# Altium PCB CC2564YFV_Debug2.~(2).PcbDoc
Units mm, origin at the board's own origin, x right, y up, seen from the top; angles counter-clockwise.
Board outline 229.87 x 45.72 mm, 2 copper layers (Top Layer, Bottom Layer); 42 components, 48 nets, 258 pads, 54 vias.
Unrouted connection lines stored in the file: 3.
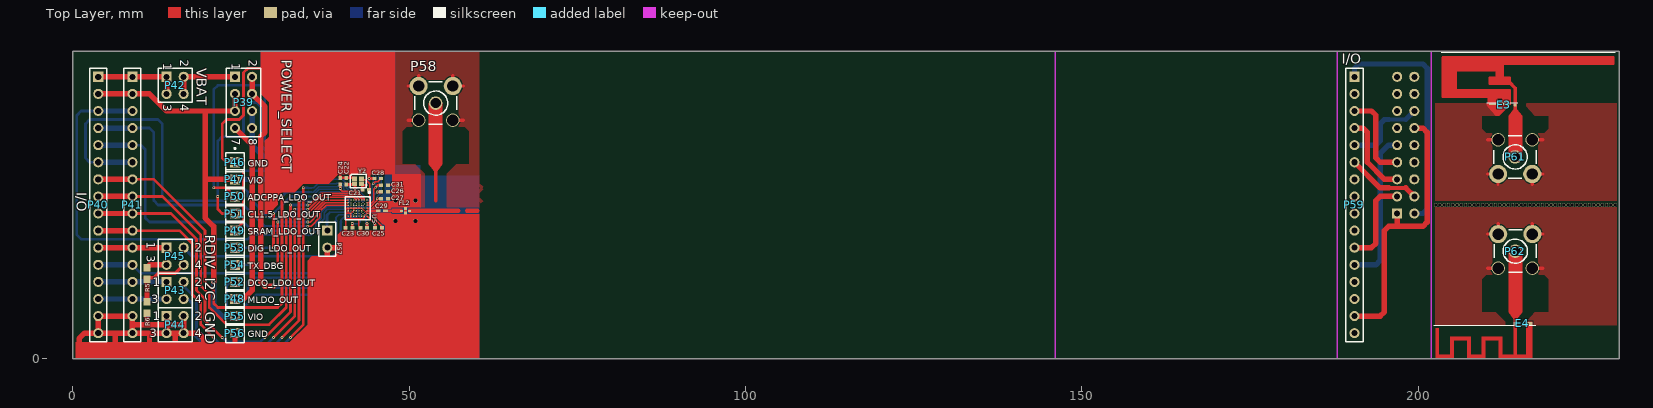
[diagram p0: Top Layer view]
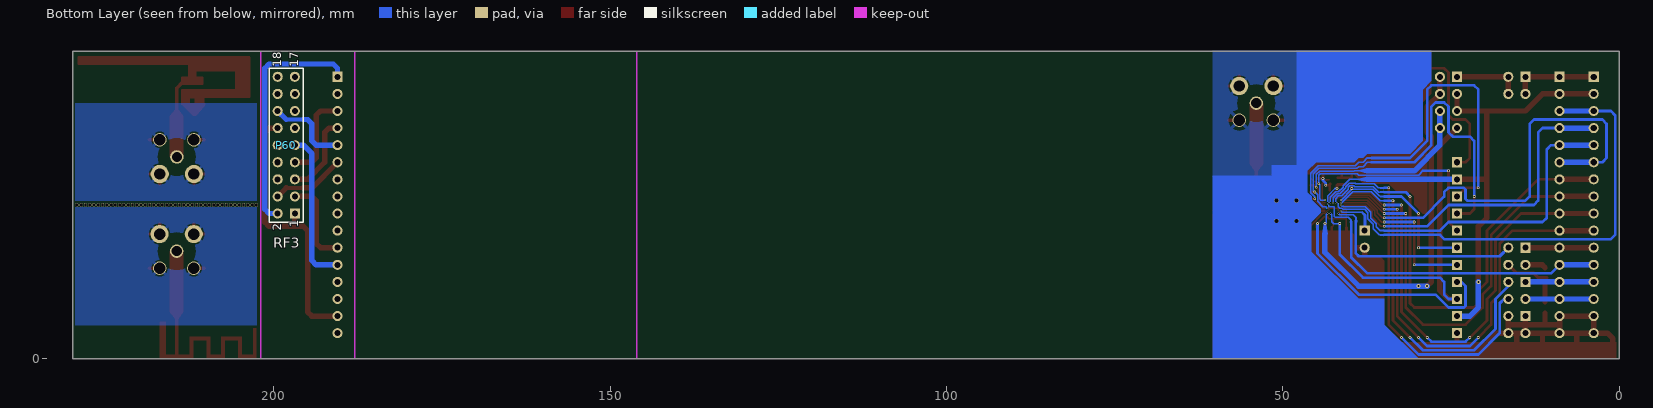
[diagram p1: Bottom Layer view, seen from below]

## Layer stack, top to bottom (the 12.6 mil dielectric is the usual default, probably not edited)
Top Solder: solder mask 0.0102, Solder Resist, Dk 3.5
Top Layer: signal copper 0.0356
Dielectric 1: dielectric 0.32, FR-4, Dk 4.8
Bottom Layer: signal copper 0.0356
Bottom Solder: solder mask 0.0102, Solder Resist, Dk 3.5

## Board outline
0,0 229.87,0 229.87,45.72 0,45.72

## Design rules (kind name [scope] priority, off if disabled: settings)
Clearance [All] p1: gap=0.1
ComponentClearance [All] p1 off: gap=0.1 collisioncheckmode=3 verticalgap=0.1 showdistances=FALSE
HoleSize [All] p1: absolutevalues=TRUE maxlimit=2.54 minlimit=0.1 maxpercent=80.000 minpercent=20.000
HoleToHoleClearance [All] p1: gap=0.1 allowstackedmicrovias=TRUE
MinimumSolderMaskSliver [All] p1: minsoldermaskwidth=0.1
PolygonConnect [All] p1: connectstyle=Relief reliefconductorwidth=0.5 reliefentries=4 polygonreliefangle="45 Angle" airgapwidth=0.2
RoutingVias [All] p1: holewidth=0.2 width=0.25 viastyle="Through Hole" minholewidth=0.1 minwidth=0.25 maxholewidth=0.2 maxwidth=0.45
SilkToSilkClearance [All] p1: silktosilkclearance=0.1
SilkToSolderMaskClearance [IsPad] p1 off: minsilkscreentomaskgap=0.1 clearancetoexposedcopper=TRUE
SolderMaskExpansion [All] p1: expansion=0.102
Width [All] p1: maxlimit=6 minlimit=0.1 preferedwidth=0.2
23 further rules are at their usual default settings.

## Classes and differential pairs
component class CC2564YFV_Debug2_RF: C21 C22 C23 C24 C25 C26 C27 C28 C29 C30 C31 FL2 P39 P40 P41 P42 P43 P44 P45 P46 P47 P48 P49 P50 P51 P52 P53 P54 P55 P56 P57 P58 R5 R6 U5 Y2
component class CC2564YFV_Debug2_Add: E3 E4 P59 P60 P61 P62

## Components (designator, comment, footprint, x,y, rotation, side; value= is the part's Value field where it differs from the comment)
C21 "Cap Semi 8 pF" 0402 43.56,25.1 r0 top
C22 "Cap Semi 8 pF" 0402 40.66,26.4 r270 top
C23 "C1005X5R1A105K050BB" 0402 41.06,19.5 r0 top
C24 "C1005X7R1H104M050BB" 0402 39.76,26.4 r270 top
C25 "C1005X7R1H104M050BB" 0402 45.46,19.5 r180 top
C26 "C1005X7R1H104M050BB" 0402 46.36,24.8 r180 top
C27 "C1005X7R1H104M050BB" 0402 46.36,23.8 r180 top
C28 "C1005X7R1H104M050BB" 0402 45.36,26.8 r0 top
C29 "GRM0335C1E220JA01D" 1-0201 45.96,22 r0 top
C30 "C1005X7R1H104M050BB" 0402 43.26,19.5 r0 top
C31 "C1005X5R1A105K050BB" 0402 46.36,25.8 r180 top
E3 "Inverted F Antenna" Inverted_F_Antenna 214.38,37.7 r0 top
E4 "Meandered IFA" Meandered_IFA 216.95,5 r180 top
FL2 "FI105L250014" FL105_Electrodes 49.46,22 r0 top
P39 "POWER_SELECT" HDR2X4 24.13,41.91 r270 top
P40 "I/O" HDR1X16 3.81,41.91 r270 top
P41 "I/O" HDR1X16 8.89,41.91 r270 top
P42 "VBAT" HDR2X2 13.97,41.91 r270 top
P43 "I2C" HDR2X2 13.97,11.43 r270 top
P44 "GND" HDR2X2 13.97,6.35 r270 top
P45 "RDIV" HDR2X2 13.97,16.51 r270 top
P46 "GND" PIN1 24.13,29.21 r0 top
P47 "VIO" PIN1 24.13,26.67 r0 top
P48 "MLDO_OUT" PIN1 24.13,8.89 r0 top
P49 "SRAM_LDO_OUT" PIN1 24.13,19.05 r0 top
P50 "ADCPPA_LDO_OUT" PIN1 24.13,24.13 r0 top
P51 "CL1.5_LDO_OUT" PIN1 24.13,21.59 r0 top
P52 "DCO_LDO_OUT" PIN1 24.13,11.43 r0 top
P53 "DIG_LDO_OUT" PIN1 24.13,16.51 r0 top
P54 "TX_DBG" PIN1 24.13,13.97 r0 top
P55 "VIO" PIN1 24.13,6.35 r0 top
P56 "GND" PIN1 24.13,3.81 r0 top
P57 "G5" HDR1X2 37.846,19.05 r270 top
P58 "SMA" SMA#1 53.96,38 r0 top
P59 "I/O" HDR1X16 190.5,41.91 r270 top
P60 "RF3" HDR2X9 196.85,21.59 r90 bottom
P61 "SMA" SMA#2 214.38,30 r0 top
P62 "SMA" SMA#1 214.4,16 r0 top
R5 "Res Chip 10 K" 3-0603 11.049,12.7 r90 top
R6 "Res Chip 12 K" 3-0603 11.049,7.62 r90 top
U5 "CC2564YFV" "YFV (R-XBGA-N54)" 42.36,22.2 r270 top
Y2 "NX1612AA-26MHZ-TI2" XTAL_QUAD_1.6x1.2mm 42.435,26.375 r180 top

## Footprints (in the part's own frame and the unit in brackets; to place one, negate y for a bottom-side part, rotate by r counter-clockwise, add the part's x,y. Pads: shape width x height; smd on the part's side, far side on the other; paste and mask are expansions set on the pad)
1-0201 [mm] "Chip Resistor; Body 0.6 x 0.3 mm (LxW typ)"
  rect 0.7x0.4 smd: 1(-0.525,0) 2(0.525,0)
3-0603 [mm] "Chip Resistor; Body 1.6 x 0.9 mm (LxW typ)"
  rect 1.1x1 smd: 1(-0.85,0) 2(0.85,0)
0402 [mm] "Chip Capacitor, Body 1.0x0.5mm, IPC High Density"
  rect 0.6x0.5 smd: 1(-0.5,0) 2(0.5,0)
  body extent -0.55,-0.3 0.55,0.3, height 1.3
FL105_Electrodes [mm]
  round 0.6 hole 0.6: 1(-1.5,1.5) 1(1.5,1.5) 3(-1.5,-1.5) 3(1.5,-1.5)
  rect 0.4x0.45 smd: 1(0,0.35) 3(0,-0.35)
  rect 0.45x0.3 smd: 2(0.575,0) 4(-0.575,0)
  Top Layer region: -0.2,-0.5 0.2,-0.5 0.2,0.5 -0.2,0.5
  Top Layer region: 0.5,-0.3 2,-0.3 2,0.3 0.5,0.3
  Top Layer region: -2,-0.3 -0.5,-0.3 -0.5,0.3 -2,0.3
  Top Layer region: -2,-2 2,-2 2,-0.5 -2,-0.5
  Top Layer region: -2,0.5 2,0.5 2,2 -2,2
  Top Layer region: -0.5,0.3 -0.425,0.15 -0.5,0.15
  Top Layer region: 0.425,0.15 0.5,0.3 0.5,0.15
  Top Layer region: -0.425,-0.15 -0.5,-0.3 -0.5,-0.15
  Top Layer region: 0.425,-0.15 0.5,-0.3 0.5,-0.15
HDR1X2 [mm] "Connector; Header; 2 Position"
  rect 1.5x1.5 hole 0.9: 1(0,0)
  round 1.5 hole 0.9: 2(2.54,0)
  silkscreen extent -1.27,-1.27 3.81,1.27
HDR1X16 [mm] "Connector; Header; 16 Position"
  rect 1.5x1.5 hole 0.9: 1(0,0)
  round 1.5 hole 0.9: 2(2.54,0) 3(5.08,0) 4(7.62,0) 5(10.16,0) 6(12.7,0) 7(15.24,0) 8(17.78,0) 9(20.32,0) 10(22.86,0) 11(25.4,0) 12(27.94,0) 13(30.48,0) 14(33.02,0) 15(35.56,0) 16(38.1,0)
  silkscreen extent -1.27,-1.27 39.37,1.27
HDR2X2 [mm] "Connector; Header; 2x2 Position"
  rect 1.5x1.5 hole 0.9: 1(0,0)
  round 1.5 hole 0.9: 2(0,2.54) 3(2.54,0) 4(2.54,2.54)
  silkscreen extent -1.27,-1.27 3.81,3.81
HDR2X4 [mm] "Connector; Header; 4x2 Position"
  rect 1.5x1.5 hole 0.9: 1(0,0)
  round 1.5 hole 0.9: 2(0,2.54) 3(2.54,0) 4(2.54,2.54) 5(5.08,0) 6(5.08,2.54) 7(7.62,0) 8(7.62,2.54)
  silkscreen extent -1.27,-1.27 8.89,3.81
HDR2X9 [mm] "Connector; Header; 9x2 Position"
  rect 1.5x1.5 hole 0.9: 1(0,0)
  round 1.5 hole 0.9: 2(0,2.54) 3(2.54,0) 4(2.54,2.54) 5(5.08,0) 6(5.08,2.54) 7(7.62,0) 8(7.62,2.54) 9(10.16,0) 10(10.16,2.54) 11(12.7,0) 12(12.7,2.54) 13(15.24,0) 14(15.24,2.54) 15(17.78,0) 16(17.78,2.54) 17(20.32,0) 18(20.32,2.54)
  silkscreen extent -1.27,-1.27 21.59,3.81
Inverted_F_Antenna [mm]
  round 0.46 smd mask+0: 1(0,0)
  rect 1x0.3 smd paste+0 mask+0: 2(-1.272,0.165) 3(-3.367,0.183)
  Top Layer region: -10.77,1.092 -10.237,1.092 -4.039,1.067 -4.039,0.127 -4.032,0.088 -4.009,0.055 -3.976,0.033 -3.937,0.025 -3.937,0.025 -2.788,0.025 -2.749,0.033 -2.716,0.055 -2.694,0.088 -2.686,0.127 -2.686,0.127 -2.686,1.025 -1.89,1.025 -1.89,0.127 -1.882,0.088 -1.86,0.055 -1.827,0.033 -1.788,0.025 -1.788,0.025 -0.788,0.025 -0.767,0.027 -0.747,0.033 -0.747,0.033 -0.702,0.051 -0.669,0.087 -0.658,0.135 -0.658,0.135 -0.658,0.135 -0.658,0.135 -0.658,0.135 -0.66,2.23 -0.67,2.274 -0.698,2.309 -0.698,2.309 -0.698,2.309 -0.721,2.338 -0.752,2.356 -0.788,2.363 -0.788,2.363 -8.686,2.363 -8.686,5.025 -2.89,5.025 -2.89,4.229 -3.788,4.229 -3.827,4.221 -3.86,4.199 -3.882,4.166 -3.89,4.127 -3.89,4.127 -3.89,3.127 -3.882,3.088 -3.86,3.055 -3.827,3.033 -3.788,3.025 -3.788,3.025 -0.83,3.025 -0.231,2.426 -0.231,0 -0.208,-0.1 -0.144,-0.18 -0.052,-0.225 0.051,-0.225 0.143,-0.18 0.207,-0.1 0.23,0 0.23,0 0.23,2.521 0.212,2.61 0.162,2.685 0.162,2.685 -0.686,3.533 -0.686,4.127 -0.694,4.166 -0.716,4.199 -0.749,4.221 -0.788,4.229 -0.788,4.229 -1.686,4.229 -1.686,6.025 14.63,6.025 14.669,6.033 14.702,6.055 14.724,6.088 14.732,6.127 14.732,6.127 14.732,7.137 14.724,7.176 14.702,7.21 14.669,7.232 14.63,7.239 14.63,7.239 -10.77,7.239 -10.809,7.232 -10.842,7.21 -10.864,7.176 -10.872,7.137 -10.872,7.137 -10.872,1.194 -10.864,1.155 -10.842,1.122 -10.809,1.1 -10.77,1.092
  silkscreen extent -11,0.34 14.9,7.86
Meandered_IFA [mm] "Meandered Inverted F Antenna"
  rect 0.5x0.5 smd mask+0: 1(2.55,-0.25)
  rect 0.9x0.5 smd mask+0: 2(0.45,-0.25)
  Top Layer region: 0,-0.5 0,4.89 5,4.89 5,2.25 7,2.25 7,4.89 9.7,4.89 9.7,2.25 11.7,2.25 11.7,4.89 14.4,4.89 14.4,0.45 13.9,0.45 13.9,4.39 12.2,4.39 12.2,1.75 9.2,1.75 9.2,4.39 7.5,4.39 7.5,1.75 4.5,1.75 4.5,4.39 2.8,4.39 2.8,-0.5 2.3,-0.5 2.3,4.39 0.9,4.39 0.9,-0.5
  silkscreen extent -0.5,0 14.7,0
PIN1 [mm] "Connector; Plug"
  rect 1.5x1.5 hole 0.9: 1(0,0)
  silkscreen extent -1.4,-1.4 1.4,2.17
SMA#1 [mm] "Connector; SMA Generic"
  round 2 hole 1.5: 1(0,0)
  round 2 hole 1.7: 2(-2.54,-2.54) 2(2.54,-2.54)
  round 2.7 hole 1.7: 2(-2.54,2.54) 2(2.54,2.54)
  silkscreen extent -3.15,-3.15 3.15,3.15
SMA#2 [mm] "Connector; SMA Generic"
  round 2 hole 1.5: 1(0,0)
  round 2.7 hole 1.7: 2(-2.54,-2.54) 2(2.54,-2.54)
  round 2 hole 1.7: 2(-2.54,2.54) 2(2.54,2.54)
  silkscreen extent -3.15,-3.15 3.15,3.15
XTAL_QUAD_1.6x1.2mm [mm]
  rect 0.75x0.65 smd: 1(-0.525,-0.375) 2(0.525,-0.375) 3(0.525,0.375) 4(-0.525,0.375)
  silkscreen extent -1.2,-1.02 1.2,0.98
"YFV (R-XBGA-N54)" [mm] "BGA, 54-Balls, Pitch 0.4mm"
  round 0.2 smd: A1(-1.4,1.4) A2(-1,1.4) A3(-0.6,1.4) A4(-0.2,1.4) A5(0.2,1.4) A6(0.6,1.4) A7(1,1.4) B1(-1.4,1) B2(-1,1) B3(-0.6,1) B4(-0.2,1) B6(0.6,1) B7(1,1) C1(-1.4,0.6) C2(-1,0.6) C3(-0.6,0.6) C4(-0.2,0.6) C5(0.2,0.6) C6(0.6,0.6) C7(1,0.6) D1(-1.4,0.2) D2(-1,0.2) D3(-0.6,0.2) D4(-0.2,0.2) D5(0.2,0.2) D6(0.6,0.2) D7(1,0.2) E1(-1.4,-0.2) E2(-1,-0.2) E3(-0.6,-0.2) E4(-0.2,-0.2) E5(0.2,-0.2) E6(0.6,-0.2) E7(1,-0.2) F1(-1.4,-0.6) F2(-1,-0.6) F3(-0.6,-0.6) F4(-0.2,-0.6) F5(0.2,-0.6) F6(0.6,-0.6) F7(1,-0.6) G1(-1.4,-1) G2(-1,-1) G3(-0.6,-1) G4(-0.2,-1) G5(0.2,-1) G6(0.6,-1) G7(1,-1) H1(-1.4,-1.4) H2(-1,-1.4) H3(-0.6,-1.4) H4(-0.2,-1.4) H5(0.2,-1.4) H7(1,-1.4)
  silkscreen extent -2.65,-1.88 1.52,1.88, body extent -1.91,-1.91 1.52,1.91, height 0.5

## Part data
C21 C22: "Chip Capacitor, 8 pF"
C23 C31: "1.0 uF/10 V 0402"
C24 C25 C26 C27 C28 C30: "0.1 uF/50 V 0402"
C29: "22 pF/25 V 0201"
E3: "Inverted F Antenna (Design Note DN0007; SWRU120B)"
E4: "Meandered Inverted F Antenna (Application Note AN043; SWRA117D)"
FL2: "2.4 GHz Low Pass Filter"
P39: library part "Header 4X2", "Header, 4-Pin, Dual row"
P40 P41 P59: library part "Header 16", "Header, 16-Pin"
P42 P43 P44 P45: library part "Header 2X2", "Header, 2-Pin, Dual row"
P46 P47 P48 P49 P50 P51 P52 P53 P54 P55 P56: library part Plug, "Plug"
P57: library part "Header 2", "Header, 2-Pin"
P58 P61 P62: "SMA Generic Connector"
P60: library part "Header 9X2", "Header, 9-Pin, Dual row"
R5: "Chip Resistor, 10 K"
R6: "Chip Resistor, 12 K"
U5: "CC2564, 54-balls DSBGA"
Y2: "Crystal Oscillator 26 MHz"

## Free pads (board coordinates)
  round 0.5 hole 0.5 paste+0 mask+0: 0(202.565,22.86) 0(203.2,22.86) 0(203.835,22.86) 0(204.47,22.86) 0(205.105,22.86) 0(205.74,22.86) 0(206.375,22.86) 0(207.01,22.86) 0(207.645,22.86) 0(208.28,22.86) 0(208.915,22.86) 0(209.55,22.86) 0(210.185,22.86) 0(210.82,22.86) 0(211.455,22.86) 0(212.09,22.86) 0(212.725,22.86) 0(213.36,22.86) 0(213.995,22.86) 0(214.63,22.86) 0(215.265,22.86) 0(215.9,22.86) 0(216.535,22.86) 0(217.17,22.86) 0(217.805,22.86) 0(218.44,22.86) 0(219.075,22.86) 0(219.71,22.86) 0(220.345,22.86) 0(220.98,22.86) 0(221.615,22.86) 0(222.25,22.86) 0(222.885,22.86) 0(223.52,22.86) 0(224.155,22.86) 0(224.79,22.86) 0(225.425,22.86) 0(226.06,22.86) 0(226.695,22.86) 0(227.33,22.86) 0(227.965,22.86) 0(228.6,22.86) 0(229.235,22.86)

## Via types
v1: diameter 0.4, hole 0.2, Top Layer to Bottom Layer, 36 vias
v2: diameter 0.25, hole 0.1, Top Layer to Bottom Layer, 15 vias
v3: diameter 0.6, hole 0.3, Top Layer to Bottom Layer, 3 vias

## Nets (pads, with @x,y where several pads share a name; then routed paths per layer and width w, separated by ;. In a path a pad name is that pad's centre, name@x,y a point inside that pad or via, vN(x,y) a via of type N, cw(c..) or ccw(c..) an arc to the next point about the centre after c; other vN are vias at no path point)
ADCPPA_LDO_OUT_2: C27.2 P50.1 U5.A4 | length 60
  Top Layer w0.2: U5.A4 44.06,22.4 v1@45.26,23.6
  Top Layer w0.4: v1(20.955,25.4) 22.86,25.4 P50.1 ; v1(45.26,23.8) C27.2
  Bottom Layer w0.2: 36.83,29.845 37.465,29.845 38.1,29.21 38.735,29.21 39.245,28.7 44.76,28.7 45.86,27.6 45.86,24.7 45.26,24.1 v1(45.26,23.8)
  Bottom Layer w0.4: v1(20.955,25.4) 20.955,40.005 21.59,40.64 27.94,40.64 28.575,40.005 28.575,32.385 31.115,29.845 36.83,29.845
ANTENNA: FL2.2 P58.1 | length 12.9
  Top Layer w0.5: 53.96,23.45 53.96,29.5
  Top Layer w0.6: 50.46,22 57.31,22
AUD_CLK_2: P40.8 P41.8 U5.E1 | length 68
  Top Layer w0.2: v1(34.925,21.59) 34.95,21.59 37.36,24 41.784,24 42.16,23.624 U5.E1
  Top Layer w0.4: P41.8 13.335,24.13 19.05,18.415 19.05,10.795 20.32,9.525 20.32,7.62 22.86,5.08 29.21,5.08 31.75,7.62 v1(31.75,21.59)
  Top Layer w0.8: P40.8 P41.8
  Bottom Layer w0.4: v1(31.75,21.59) v1(34.925,21.59)
AUD_FSYNC_2: P40.7 P41.7 U5.E2 | length 70.2
  Top Layer w0.4: P41.7 12.065,26.67 19.685,19.05 19.685,11.43 20.955,10.16 20.955,8.255 21.59,7.62 30.48,7.62 31.115,8.255 v1(31.115,24.13)
  Top Layer w0.8: P40.7 P41.7
  Bottom Layer w0.2: 34.925,24.765 35.725,24.765 36.56,25.6 39.36,25.6 39.46,25.7 40.06,25.7 40.26,25.5 40.26,25.2 41.26,24.2 41.76,24.2 42.16,23.8 v2(42.16,23.2)
  Bottom Layer w0.4: v1(31.115,24.13) 31.75,24.765 34.925,24.765
AUD_IN_2: P40.9 P41.9 U5.C1 | length 72.3
  Top Layer w0.2: v1(34.925,22.86) 35.22,22.86 36.96,24.6 42.136,24.6 42.96,23.776 U5.C1
  Top Layer w0.4: P41.9 14.605,21.59 18.415,17.78 18.415,10.16 19.685,8.89 19.685,5.715 v1(22.225,3.175) ; v1(28.575,3.175) 32.385,6.985 v1(32.385,22.86)
  Top Layer w0.8: P40.9 P41.9
  Bottom Layer w0.4: v1(22.225,3.175) 22.86,2.54 27.94,2.54 v1(28.575,3.175) ; v1(32.385,22.86) v1(34.925,22.86)
AUD_OUT_2: P40.10 P41.10 U5.D1 | length 71.1
  Top Layer w0.2: v1(34.925,22.225) 35.085,22.225 37.16,24.3 41.96,24.3 42.56,23.7 U5.D1
  Top Layer w0.4: P41.10 15.875,19.05 17.78,17.145 17.78,9.525 19.05,8.255 19.05,5.08 v1(20.955,3.175) ; v1(29.845,3.175) 33.02,6.35 v1(33.02,22.225)
  Top Layer w0.8: P40.10 P41.10
  Bottom Layer w0.4: v1(20.955,3.175) 22.225,1.905 28.575,1.905 v1(29.845,3.175) ; v1(33.02,22.225) v1(34.925,22.225)
BT_CTS_2: P40.6 P41.6 U5.H1 | length 68.1
  Top Layer w0.2: v1(34.925,20.955) 35.215,20.955 35.96,21.7 35.96,22.1 37.46,23.6 U5.H1
  Bottom Layer w0.4: P40.6 2.54,29.21 1.905,29.845 1.905,34.925 2.54,35.56 12.7,35.56 13.335,34.925 13.335,24.13 13.97,23.495 22.606,23.495 22.86,23.749 22.86,25.146 23.114,25.4 25.4,25.4 26.035,24.765 26.035,24.13 29.21,20.955 v1(34.925,20.955)
  Bottom Layer w0.8: P40.6 P41.6
BT_CTS_3: P59.6 P60.4 | length 11
  Top Layer w0.6: 195.58,25.4 198.12,25.4
  Top Layer w0.8: P59.6 194.31,25.4 195.58,25.4 ; 198.12,25.4 P60.4
BT_RTS_2: P40.5 P41.5 U5.G3 | length 51.1
  Bottom Layer w0.2: 34.925,19.05 35.56,19.05 36.16,19.65 36.16,20.1 36.96,20.9 36.96,21.8 37.76,22.6 40.96,22.6 41.06,22.7 41.26,22.7 v2(41.36,22.8)
  Bottom Layer w0.4: P41.5 10.16,31.75 10.795,31.115 10.795,20.955 11.43,20.32 25.4,20.32 26.67,19.05 34.925,19.05
  Bottom Layer w0.8: P40.5 P41.5
BT_RTS_3: P59.5 P60.14 | length 12.5
  Bottom Layer w0.6: 195.58,35.56 198.12,35.56
  Bottom Layer w0.8: P59.5 193.675,31.75 194.31,32.385 194.31,34.925 194.945,35.56 195.58,35.56 ; 198.12,35.56 P60.14
BT_RX_2: P40.4 P41.4 U5.H3 | length 50.8
  Top Layer w0.2: v1@35.06,19.7 35.46,19.7 36.76,21 36.76,21.9 37.66,22.8 U5.H3
  Bottom Layer w0.4: P41.4 11.43,34.29 12.065,33.655 12.065,23.495 12.7,22.86 25.4,22.86 28.575,19.685 v1(34.925,19.685)
  Bottom Layer w0.8: P40.4 P41.4
BT_RX_3: P59.4 P60.5 | length 12.1
  Top Layer w0.8: P59.4 191.77,34.29 192.405,33.655 192.405,29.21 194.945,26.67 P60.5
BT_SHUTD_2: P40.12 P41.12 U5.B3 | length 48.3
  Bottom Layer w0.2: 39.86,20.3 39.86,20.6 40.26,21 42.26,21 42.36,21.1 42.36,22.5 42.46,22.6 43.1,22.6 43.3,22.8 v2(43.36,22.8)
  Bottom Layer w0.4: P41.12 10.16,12.7 37.465,12.7 39.86,15.095 39.86,20.3
  Bottom Layer w0.8: P40.12 P41.12
BT_SHUTD_3: P59.12 P60.9 | length 23
  Bottom Layer w0.8: P59.12 193.675,13.97 194.31,14.605 194.31,30.48 195.58,31.75 P60.9
BT_TX_2: P40.3 P41.3 U5.F2 | length 70.6
  Bottom Layer w0.2: 34.925,18.415 35.675,18.415 36.56,19.3 36.56,20 37.36,20.8 37.36,21.7 37.86,22.2 41.06,22.2 41.26,22.4 41.56,22.4 41.76,22.6 v2(41.76,23.2)
  Bottom Layer w0.4: P40.3@3.175,36.83 1.27,36.83 0.635,36.195 0.635,18.415 1.27,17.78 26.035,17.78 26.67,18.415 34.925,18.415
  Bottom Layer w0.8: P40.3 P41.3
BT_TX_3: P59.3 P60.7 | length 13.2
  Top Layer w0.8: P59.3 193.04,36.83 193.675,36.195 193.675,29.845 194.31,29.21 P60.7
CL1.5_LDO_IN_2: C30.2 P39.2 P39.4 U5.B6 | length 57.5
  Top Layer w0.4: C30.2 v1(43.76,20.1)
  Top Layer w0.8: P39.2 P39.4 28.575,37.465 28.575,33.655 27.94,33.02 27.94,11.43 v3(28.575,10.795) v3(29.845,10.795)
  Bottom Layer w0.2: v2(43.36,21.6) 43.56,21.4 43.56,20.3 v1(43.76,20.1)
  Bottom Layer w0.4: 43.76,18.5 v1(43.76,20.1)
  Bottom Layer w0.8: v3(28.575,10.795) 38.735,10.795 43.76,15.82 43.76,18.5
CL1.5_LDO_OUT_2: C26.2 P51.1 U5.B4 | length 56
  Top Layer w0.4: v1(21.59,24.13) 21.59,22.225 22.225,21.59 P51.1 ; v1(45.26,24.8) C26.2
  Bottom Layer w0.2: 36.83,29.21 37.465,29.21 38.1,28.575 38.735,28.575 39.01,28.3 44.66,28.3 45.46,27.5 45.46,25 v1(45.26,24.8) 44.86,24.4 44.86,23.4 44.06,22.6 43.66,22.6 43.46,22.4 v2(43.36,22.4)
  Bottom Layer w0.4: v1(21.59,24.13) 21.59,32.385 22.225,33.02 24.765,33.02 25.4,33.655 25.4,37.465 26.035,38.1 27.305,38.1 27.94,37.465 27.94,31.75 30.48,29.21 36.83,29.21
DCO_LDO_OUT_2: C25.2 P52.1 U5.A7 | length 36.4
  Top Layer w0.2: U5.A7 v1@44.96,20
  Top Layer w0.4: C25.2@44.96,19.6 v1@44.96,20
  Bottom Layer w0.4: P52.1 23.495,11.43 22.86,10.795 22.86,7.874 23.114,7.62 25.4,7.62 27.305,9.525 38.735,9.525 44.86,15.65 v1(44.86,20.1)
DIG_LDO_OUT_2: C24.2 P53.1 U5.B1 U5.G1 | length 29.6
  Top Layer w0.2: v1@39.76,25.2 40.06,24.9 42.26,24.9 43.36,23.8 U5.B1
  Top Layer w0.4: v1(29.845,16.51) v1(29.845,21.59) ; v1(39.76,25.3) C24.2 C24.2@39.76,26
  Bottom Layer w0.2: 34.925,24.13 35.56,24.13 ; 35.59,24.13 36.66,25.2 v1@39.76,25.2 ; v1(39.76,25.3) v1@39.76,25.2 ; v2(41.36,23.6) v1@39.76,25.2
  Bottom Layer w0.4: P53.1 v1(29.845,16.51) ; v1(29.845,21.59) 32.385,24.13 34.925,24.13
GND_2: C21.1 C22.1 C23.1 C24.1 C25.1 C26.1 C27.1 C28.1 C30.1 C31.1 FL2.1 FL2.3 P40.15 P40.16 P41.15 P41.16 P44.1 P44.2 P44.3 P44.4 P46.1 P56.1 P57.2 P58.2 R6.1 U5.A6 U5.B7 U5.C4 U5.D4 U5.E4 U5.F4 U5.F5 U5.G4 U5.G6 U5.G7 U5.H4 U5.H5 Y2.2 Y2.4 | length 115.3
  Top Layer w0.1: U5.C4 U5.A6
  Top Layer w0.11: 41.46,21.7 41.66,21.9 ; 43.46,21.3 43.66,21.5
  Top Layer w0.15: U5.G6 41.46,21.7 ; 41.66,21.9 U5.F5
  Top Layer w0.18: U5.B7 43.46,21.3 ; 43.66,21.5 U5.A6
  Top Layer w0.2: C23.1 40.56,20.8 ; 40.96,21.6 U5.H5 U5.H4 ; U5.F5 U5.F4 ; C30.1@42.56,19.7 42.56,20.8 ; U5.C4 U5.D4 U5.E4 U5.F4 ; U5.B7 43.36,21 43.16,20.8 42.56,20.8 ; U5.A6 44.06,21.6 45.96,19.7 C25.1 ; 40.56,20.8 41.36,20.8 ; 40.56,20.8 40.56,21.6 ; 40.56,21.6 U5.G6 U5.G7 41.36,20.8 ; 40.56,21.6 40.56,22.2 40.76,22.4 U5.H4 ; U5.H4 U5.G4 U5.F4 ; 41.36,20.8 42.56,20.8
  Top Layer w0.3: C27.1 47.76,23.8 ; C26.1 47.66,24.8 ; C31.1 47.76,25.8
  Top Layer w0.4: P46.1 22.86,29.21 22.225,29.845 22.225,34.925 22.86,35.56 24.765,35.56 25.4,36.195 25.4,42.545 26.035,43.18 29.845,43.18 ; 39.76,27.5 C24.1 Y2.2@41.81,26.9 ; 40.56,18.495 C23.1 ; 41.26,26.9 41.26,27.5 ; 42.76,18.495 C30.1 ; Y2.4 Y2.4@43.06,25.9 ; C21.1 Y2.4@43.06,25.9 ; v1(43.66,25.8) 43.16,25.8 Y2.4@43.06,25.9 ; 44.06,27.5 v1(44.06,26.8) C28.1 ; 45.96,18.495 C25.1
  Top Layer w0.5: 49.862,35.46 P58.2@51.42,35.46 ; 49.862,40.54 51.42,40.54 51.42,42.098 ; P58.2@56.5,35.46 58.057,35.46 ; 56.5,42.098 56.5,40.54 58.057,40.54
  Top Layer w0.8: 0.96,2.5 0.96,3 1.77,3.81 P40.16 ; 6.35,2.54 6.35,3.81 ; 11.049,5.461 R6.1 ; 11.43,2.54 11.43,3.81 ; P44.1 13.97,5.08 ; 15.24,2.54 15.24,3.81 ; P44.2 16.51,5.08 ; 19.46,2.5 19.46,3 18.65,3.81 P44.4 ; 24.13,2.54 P56.1 ; 37.846,14.224 P57.2 39.37,16.51 ; P40.16 6.35,3.81 ; P40.16 P40.15 P41.15 8.89,5.08 ; 6.35,3.81 P41.16 ; P41.16 11.43,3.81 ; P41.16 8.89,5.08 ; 8.89,5.08 13.97,5.08 ; 11.43,3.81 P44.3 ; P44.3 15.24,3.81 ; P44.3 13.97,5.08 ; 13.97,5.08 16.51,5.08 ; 15.24,3.81 P44.4 ; P44.4 16.51,5.08
  Bottom Layer w0.4: v1(43.66,25.8) 43.66,26.1 44.06,26.5 v1(44.06,26.8)
GND_3: P59.15 P59.16 P60.1 P60.12 | length 41.1
  Top Layer w0.8: P59.15 194.31,6.35 194.945,6.985 194.945,19.05 195.58,19.685 196.85,19.685 ; P60.1 196.85,19.685 ; P60.12 200.66,34.29 201.295,33.655 201.295,20.32 200.66,19.685 196.85,19.685
I2C_SCL_2: P43.2 U5.G2 | length 52.9
  Top Layer w0.4: v1(31.115,3.175) 33.655,5.715 v1(33.655,23.495)
  Bottom Layer w0.2: 34.925,23.495 35.56,23.495 36.865,24.8 39.66,24.8 41.26,23.2 v2(41.36,23.2)
  Bottom Layer w0.4: P43.2 16.51,10.795 18.415,8.89 18.415,4.445 21.59,1.27 29.21,1.27 v1(31.115,3.175) ; v1(33.655,23.495) 34.925,23.495
I2C_SDA_2: P43.4 U5.D2 | length 56.3
  Top Layer w0.4: v1(32.385,3.175) 34.29,5.08 v1(34.29,25.4)
  Bottom Layer w0.2: 34.925,25.4 35.86,25.4 36.46,26 39.16,26 39.26,26.1 40.16,26.1 40.66,25.6 40.66,25.4 41.56,24.5 41.96,24.5 42.56,23.9 v2(42.56,23.2)
  Bottom Layer w0.4: P43.4 17.145,8.89 17.78,8.255 17.78,3.81 20.955,0.635 29.845,0.635 v1(32.385,3.175) ; v1(34.29,25.4) 34.925,25.4
MLDO_IN_2: C31.2 P39.6 P39.8 U5.A3 | length 31.5
  Top Layer w0.2: U5.A3 44.036,22.8 44.76,23.524 44.76,25.2 v1(45.06,25.5)
  Top Layer w0.4: v1(45.06,25.5) 45.36,25.8 C31.2
  Bottom Layer w0.2: 37.465,27.94 39.37,27.94 ; 39.37,27.9 44.56,27.9 45.06,27.4 v1(45.06,25.5)
  Bottom Layer w0.8: P39.6 26.67,31.75 30.48,27.94 37.465,27.94
MLDO_OUT_2: C23.2 P39.7 P48.1 U5.C6 | length 57.3
  Top Layer w0.4: C23.2 v1(41.56,20.1)
  Top Layer w0.8: P48.1 25.4,8.89 26.67,10.16 26.67,31.75 P39.7
  Bottom Layer w0.2: v1(41.56,20.1) 42.46,20.1 42.76,20.4 42.76,21.4 v2(42.96,21.6)
  Bottom Layer w0.4: P48.1 25.4,8.89 26.035,9.525 26.035,11.43 26.67,12.065 38.1,12.065 41.56,15.525 v1(41.56,20.1)
NetE3_1: E3.1 P61.1 | length 2.2
  Top Layer w0.5: 214.4,35.5 E3.1@214.4,37.75
NetE3_2: E3.2 E3.3 P61.2 | length 9.3
  Top Layer w0.5: 210.283,27.46 211.84,27.46 211.84,25.903 ; 210.283,32.54 P61.2@211.84,32.54 ; 216.92,25.903 216.92,27.46 218.478,27.46 ; P61.2@216.92,32.54 218.478,32.54
NetE4_1: E4.1 P62.1 | length 2.2
  Top Layer w0.5: E4.1 214.4,7.5
NetE4_2: E4.2 P62.2 | length 9.3
  Top Layer w0.5: 210.303,13.46 P62.2@211.86,13.46 ; 210.303,18.54 211.86,18.54 211.86,20.098 ; P62.2@216.94,13.46 218.498,13.46 ; 216.94,20.098 216.94,18.54 218.498,18.54
NetP45_3: P45.3 R5.2 | length 3.1
  Top Layer w0.8: R5.2 11.469,13.97 P45.3
NetP45_4: P45.4 R5.1 R6.2 | length 9.9
  Top Layer w0.5: R5.1@10.795,12.065 12.065,12.065 12.7,12.7 15.24,12.7 P45.4
  Top Layer w0.8: R6.2 R5.1
NetP57_1: P57.1 U5.G5 | length 6.1
  Bottom Layer w0.2: 37.815,21.355 38.26,21.8 41.16,21.8 v2(41.36,22)
  Bottom Layer w0.4: P57.1@37.815,19.055 37.815,21.355
P40_1: P40.1 P41.1 P42.1 P42.3 | length 12.7
  Top Layer w0.8: P40.1 P41.1 P42.1 P42.3
P40_11: P40.11 P41.11 P45.1 | length 10.2
  Top Layer w0.8: P40.11 P41.11 P45.1
P40_13: P40.13 P41.13 P43.1 | length 10.2
  Bottom Layer w0.8: P40.13 P41.13 P43.1
P40_14: P40.14 P41.14 P43.3 | length 10.2
  Bottom Layer w0.8: P40.14 P41.14 P43.3
RF: C29.2 FL2.4 | length 2.4
  Top Layer w0.4: C29.2 FL2.4
RF_IO: C29.1 U5.A5 | length 1.6
  Top Layer w0.4: 43.86,22 C29.1
SLOW_CLK_2: P45.2 U5.F6 | length 31.5
  Bottom Layer w0.2: 39.16,20.3 39.16,21 39.56,21.4 41.56,21.4 v2(41.76,21.6)
  Bottom Layer w0.4: P45.2 17.78,15.24 38.735,15.24 39.16,15.665 39.16,20.3
SLOW_CLK_3: P59.11 P60.3 | length 13.2
  Top Layer w0.8: P59.11 193.04,16.51 193.675,17.145 193.675,23.495 194.31,24.13 P60.3
SRAM_LDO_OUT_2: C28.2 P49.1 U5.A1 | length 35.1
  Top Layer w0.2: v1(44.66,26) 44.96,26.3 45.36,26.3 C28.2
  Top Layer w0.4: P49.1 25.4,20.32 v1(25.4,27.94)
  Bottom Layer w0.2: 29.21,27.94 29.845,27.305 38.735,27.305 38.93,27.5 44.46,27.5 44.66,27.3 v1(44.66,26) 44.56,25.9 44.56,23.8 44.36,23.6 v2(43.76,23.6)
  Bottom Layer w0.4: v1(25.4,27.94) 29.21,27.94
TX_DBG_2: P54.1 U5.H2 | length 24.7
  Top Layer w0.2: v1(34.925,20.32) 35.28,20.32 36.36,21.4 36.36,22 37.56,23.2 U5.H2
  Top Layer w0.4: v1(30.48,13.97) v1(30.48,20.32)
  Bottom Layer w0.4: P54.1 v1(30.48,13.97) ; v1(30.48,20.32) v1(34.925,20.32)
VBAT_2: P39.1 P42.2 P42.4 | length 10.2
  Top Layer w0.8: P42.4 P42.2 P39.1
VBAT_3: P59.1 P60.2 | length 35.7
  Bottom Layer w0.8: P59.1 190.5,43.18 191.135,43.815 200.66,43.815 201.295,43.18 201.295,22.225 200.66,21.59 P60.2
VIO_2: P39.3 P39.5 P40.2 P41.2 P47.1 P55.1 U5.C2 | length 82.7
  Top Layer w0.8: P40.2 P41.2 11.43,39.37 13.97,36.83 P39.5 P39.3 ; 19.685,26.67 P47.1 ; 19.685,36.83 19.685,20.955 20.955,19.685 v3(20.955,11.43)
  Bottom Layer w0.2: 37.465,26.6 37.484,26.619 ; 37.465,26.67 40.09,26.67 41.06,25.7 41.06,25.5 41.76,24.8 42.16,24.8 42.96,24 v2(42.96,23.2)
  Bottom Layer w0.8: v3(20.955,11.43) 20.955,7.62 22.225,6.35 P55.1 ; P47.1 37.465,26.67
XTAL_M_2: C22.2 U5.B2 Y2.3 | length 4.7
  Top Layer w0.4: C22.2 41.86,25.9 41.96,25.8 v1(41.96,25.3)
  Bottom Layer w0.254: v1(41.96,25.3) 42.26,25.3 43.36,24.2 v2(43.36,23.2)
XTAL_P_2: C21.2 U5.A2 Y2.1 | length 4.3
  Top Layer w0.254: Y2.1@43.16,26.6 43.56,26.6 44.16,26 44.16,23.387 43.973,23.2 U5.A2
pads on no net: P59.2 P59.7 P59.8 P59.9 P59.10 P59.13 P59.14 P60.6 P60.8 P60.10 P60.11 P60.13 P60.15 P60.16 P60.17 P60.18 U5.C3 U5.C5 U5.C7 U5.D3 U5.D5 U5.D6 U5.D7 U5.E3 U5.E5 U5.E6 U5.E7 U5.F1 U5.F3 U5.F7 U5.H7
copper on no net: | length 1.6
  Top Layer w0.6: 58.61,22 60.16,22

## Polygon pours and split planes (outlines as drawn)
GND_2 on Bottom Layer "Bottom Layer-No Net" (solid, pour order 7): 42.06,45.8 42.06,27 60.46,27 60.46,45.8
NetE3_2 on Bottom Layer "Bottom Layer-No Net" (solid, pour order 8): 202.5,23.5 202.5,38 229.5,38 229.5,23.5
NetE4_2 on Bottom Layer "Bottom Layer-No Net" (solid, pour order 9): 202.5,22.5 202.5,5 229.5,5 229.5,22.5
GND_2 on Top Layer "Bottom Layer-No Net" (solid, pour order 10): 47.76,45.7 60.46,45.7 60.46,22.5 47.76,22.5
NetE3_2 on Top Layer "Bottom Layer-No Net" (solid, pour order 11): 202.5,23.5 229.5,23.5 229.5,38 202.5,38
NetE4_2 on Top Layer "Bottom Layer-No Net" (solid, pour order 12): 202.5,22.5 229.5,22.5 229.5,5 202.5,5

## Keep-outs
Keep-Out Layer:
  lines w0.2: 146.05,0 146.05,45.72 ; 187.96,0 187.96,45.72 ; 201.93,0 201.93,45.72

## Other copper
Top Layer:
  rectangle net GND_2: 0.46,0 47.625,2.5
  rectangle net GND_2: 47.46,0 60.46,21.5
  rectangle net GND_2: 47.46,22.5 51.76,27.5
  region net ANTENNA: 52.96,38 54.96,38 54.96,28.9 54.16,27.9 53.76,27.9 52.96,28.9
  pour cut-out: 50.56,41.5 57.36,41.5 57.36,34.5 58.254,34.497 58.96,33.786 58.96,28.9 57.01,28.9 55.61,27.5 55.61,22.5 52.31,22.5 52.31,27.5 50.91,28.9 48.96,28.9 48.96,33.786 49.669,34.497 50.56,34.5
  region net GND_2: 47.46,22.5 47.26,22.3 44.36,22.3 45.46,23.4 47.46,23.4
  region net NetE3_2: 211.5,36.1 212,36.1 213.722,37.835 213.7,38 210.135,38 210.135,37.665 210.4,37.4
  region net NetE3_1: 213.4,30 215.4,30 215.4,36.1 214.6,37.1 214.2,37.1 213.4,36.1
  pour cut-out: 211,26.7 217.8,26.6 217.8,33.5 218.7,33.5 219.4,34.2 219.4,36.1 217.3,36.1 216.05,37.5 216.05,38.2 213.6,38.2 211.5,36.1 209.4,36.1 209.4,34.2 210.1,33.5 211,33.5
  pour cut-out: 211,19.5 217.8,19.5 217.8,12.5 218.694,12.497 219.4,11.786 219.4,6.9 217.3,6.9 216.05,5.5 216.05,4.8 212.9,4.8 212.9,5.5 211.5,6.9 209.4,6.9 209.4,11.786 210.109,12.497 211,12.5
  region net NetE4_1: 213.4,16 215.4,16 215.4,6.9 214.6,5.9 214.2,5.9 213.4,6.9
  region net GND_2: 32.36,2.5 34.925,5.08 34.925,14.605 35.56,15.24 38.735,15.24 39.37,15.875 39.37,18.415 40.005,19.05 46.355,19.05 46.46,19.2 46.46,19.8 46.26,20 46.06,20 44.36,21.7 47.26,21.7 47.46,21.5 47.46,2.5
  region net GND_2: 47.86,27.4 39.46,27.4 38.1,26.035 34.29,26.035 33.02,24.765 31.115,24.765 30.48,24.13 30.48,22.86 29.21,21.59 28.575,21.59 28.575,32.385 29.21,33.02 29.21,38.1 27.96,39.4 27.96,45.7 47.86,45.7
Bottom Layer:
  region net I2C_SDA_2: 35.56,25.502 35.001,25.578 35.001,25.222 35.56,25.298
  region net AUD_FSYNC_2: 35.56,24.867 35.001,24.943 35.001,24.587 35.56,24.663
  region net DIG_LDO_OUT_2: 35.56,24.232 35.001,24.308 35.001,23.952 35.56,24.028
  region net I2C_SCL_2: 35.56,23.597 35.001,23.673 35.001,23.317 35.56,23.393
  region net BT_RTS_2: 35.56,19.152 35.001,19.228 35.001,18.872 35.56,18.948
  region net BT_TX_2: 35.56,18.517 35.001,18.593 35.001,18.237 35.56,18.313
  region net NetP57_1: 37.694,21.514 38.227,21.895 38.329,21.717 37.998,21.26
  region net SLOW_CLK_2: 38.964,20.32 39.065,21.006 39.268,20.98 39.345,20.32
  region net BT_SHUTD_2: 39.675,20.371 39.776,20.65 40.03,20.625 40.056,20.32
  region net CL1.5_LDO_IN_2: 43.36,18.5 43.56,19.9 43.96,19.9 44.16,18.5
  region net MLDO_IN_2: 38.735,28.042 37.567,28.321 37.592,27.559 38.735,27.838
  region net VIO_2: 38.735,26.772 37.567,27.051 37.592,26.289 38.735,26.568
  region net ADCPPA_LDO_OUT_2: 36.906,30.023 37.465,29.947 37.44,29.743 36.906,29.667
  region net CL1.5_LDO_OUT_2: 36.906,29.388 37.465,29.312 37.44,29.108 36.906,29.032
  region net GND_2: 27.96,45.8 27.96,41.3 29.21,40.005 29.21,32.385 31.115,30.48 37.465,30.48 38.1,29.845 38.735,29.845 39.37,29.21 45.085,29.21 46.355,27.94 46.355,24.765 45.72,24.13 45.72,22.86 51.66,22.9 51.66,28.8 47.96,28.8 47.96,45.8
  region net GND_2: 29.845,0 34.925,5.08 34.925,8.89 38.735,8.89 45.76,15.9 45.76,20.3 44.36,21.7 44.36,22.3 45.76,23.7 51.26,23.7 51.26,27.2 60.46,27.2 60.46,0
  pour cut-out: 51.174,38 ccw(c53.96,38) 53.96,35.214 ccw(c53.96,38) 56.746,38 ccw(c53.96,38) 53.96,40.786 ccw(c53.96,38)
  pour cut-out: 211.614,30 cw(c214.4,30) 214.4,32.786 cw(c214.4,30) 217.186,30 cw(c214.4,30) 214.4,27.214 cw(c214.4,30)
  pour cut-out: 211.614,16 ccw(c214.4,16) 214.4,13.214 ccw(c214.4,16) 217.186,16 ccw(c214.4,16) 214.4,18.786 ccw(c214.4,16)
